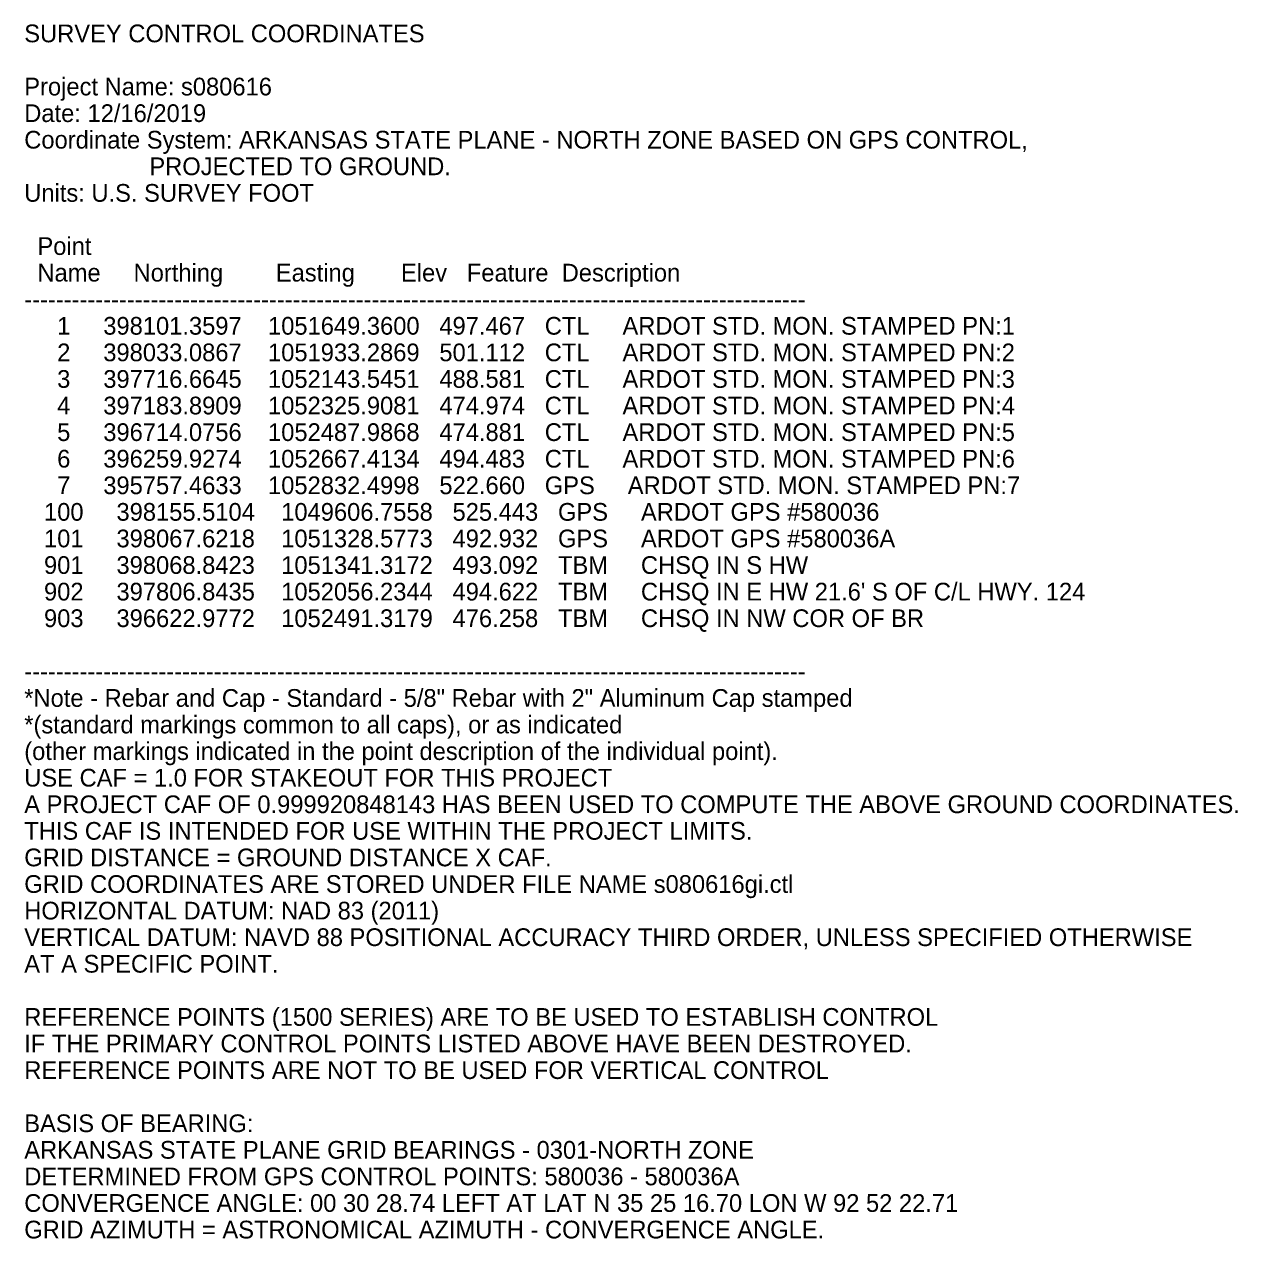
# Model space of a CAD drawing. Extents: x 1049597 to 1052842, y 395665 to 398287.
# Drawn here: x 1050194.6 to 1050536.9, y 397944.6 to 398287.2 of the extents above; entities that cross this region are included whole.
import ezdxf

# ---------------------------------------------------------------- set-up
doc = ezdxf.new("R2010")
doc.units = 0
doc.layers.add('Default', color=7, linetype='Continuous')

msp = doc.modelspace()

# ---------------------------------------------------------------- texts
at = {"layer": 'Default'}
for s, p in [('SURVEY CONTROL COORDINATES ', (1050194.6, 398282.14)), ('Project Name: s080616 ', (1050194.6, 398267.14)), ('Date: 12/16/2019 ', (1050194.6, 398259.64)), ('Coordinate System: ARKANSAS STATE PLANE - NORTH ZONE BASED ON GPS CONTROL, ', (1050194.6, 398252.14)), ('                   PROJECTED TO GROUND. ', (1050194.6, 398244.64)), ('Units: U.S. SURVEY FOOT ', (1050194.6, 398237.14)), ('  Point ', (1050194.6, 398222.14)), ('  Name     Northing        Easting       Elev   Feature  Description ', (1050194.6, 398214.64)), ('--------------------------------------------------------------------------------------------------- ', (1050194.6, 398207.14)), ('     1     398101.3597    1051649.3600   497.467   CTL    \xa0ARDOT STD. MON. STAMPED PN:1 ', (1050194.6, 398199.64)), ('     2     398033.0867    1051933.2869   501.112   CTL    \xa0ARDOT STD. MON. STAMPED PN:2 ', (1050194.6, 398192.14)), ('     3     397716.6645    1052143.5451   488.581   CTL    \xa0ARDOT STD. MON. STAMPED PN:3 ', (1050194.6, 398184.64)), ('     4     397183.8909    1052325.9081   474.974   CTL    \xa0ARDOT STD. MON. STAMPED PN:4 ', (1050194.6, 398177.14)), ('     5     396714.0756    1052487.9868   474.881   CTL    \xa0ARDOT STD. MON. STAMPED PN:5 ', (1050194.6, 398169.64)), ('     6     396259.9274    1052667.4134   494.483   CTL    \xa0ARDOT STD. MON. STAMPED PN:6 ', (1050194.6, 398162.14)), ('     7     395757.4633    1052832.4998   522.660   GPS    \xa0ARDOT STD. MON. STAMPED PN:7 ', (1050194.6, 398154.64)), ('   100     398155.5104    1049606.7558   525.443   GPS    \xa0ARDOT GPS #580036 ', (1050194.6, 398147.14)), ('   101     398067.6218    1051328.5773   492.932   GPS    \xa0ARDOT GPS #580036A ', (1050194.6, 398139.64)), ('   901     398068.8423    1051341.3172   493.092   TBM    \xa0CHSQ IN S HW ', (1050194.6, 398132.14)), ("   902     397806.8435    1052056.2344   494.622   TBM    \xa0CHSQ IN E HW 21.6' S OF C/L HWY. 124 ", (1050194.6, 398124.64)), ('   903     396622.9772    1052491.3179   476.258   TBM    \xa0CHSQ IN NW COR OF BR ', (1050194.6, 398117.14)), ('--------------------------------------------------------------------------------------------------- ', (1050194.6, 398102.14)), ('*Note - Rebar and Cap - Standard - 5/8" Rebar with 2" Aluminum Cap stamped ', (1050194.6, 398094.64)), ('*(standard markings common to all caps), or as indicated ', (1050194.6, 398087.14)), ('(other markings indicated in the point description of the individual point).  ', (1050194.6, 398079.64)), ('USE CAF = 1.0 FOR STAKEOUT FOR THIS PROJECT ', (1050194.6, 398072.14)), ('A PROJECT CAF OF 0.999920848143 HAS BEEN USED TO COMPUTE THE ABOVE GROUND COORDINATES. ', (1050194.6, 398064.64)), ('THIS CAF IS INTENDED FOR USE WITHIN THE PROJECT LIMITS. ', (1050194.6, 398057.14)), ('GRID DISTANCE = GROUND DISTANCE X CAF. ', (1050194.6, 398049.64)), ('GRID COORDINATES ARE STORED UNDER FILE NAME s080616gi.ctl  ', (1050194.6, 398042.14)), ('HORIZONTAL DATUM: NAD 83 (2011) ', (1050194.6, 398034.64)), ('VERTICAL DATUM: NAVD 88 POSITIONAL ACCURACY THIRD ORDER, UNLESS SPECIFIED OTHERWISE  ', (1050194.6, 398027.14)), ('AT A SPECIFIC POINT. ', (1050194.6, 398019.64)), ('REFERENCE POINTS (1500 SERIES) ARE TO BE USED TO ESTABLISH CONTROL ', (1050194.6, 398004.64)), ('IF THE PRIMARY CONTROL POINTS LISTED ABOVE HAVE BEEN DESTROYED. ', (1050194.6, 397997.14)), ('REFERENCE POINTS ARE NOT TO BE USED FOR VERTICAL CONTROL ', (1050194.6, 397989.64)), ('BASIS OF BEARING: ', (1050194.6, 397974.64)), ('ARKANSAS STATE PLANE GRID BEARINGS - 0301-NORTH ZONE', (1050194.6, 397967.14)), ('DETERMINED FROM GPS CONTROL POINTS: 580036 - 580036A ', (1050194.6, 397959.64)), ('CONVERGENCE ANGLE: 00 30 28.74 LEFT AT LAT N 35 25 16.70 LON W 92 52 22.71 ', (1050194.6, 397952.14)), ('GRID AZIMUTH = ASTRONOMICAL AZIMUTH - CONVERGENCE ANGLE. ', (1050194.6, 397944.64))]:
    msp.add_text(s, height=5, dxfattribs=at).set_placement(p)

doc.saveas('drawing.dxf')
